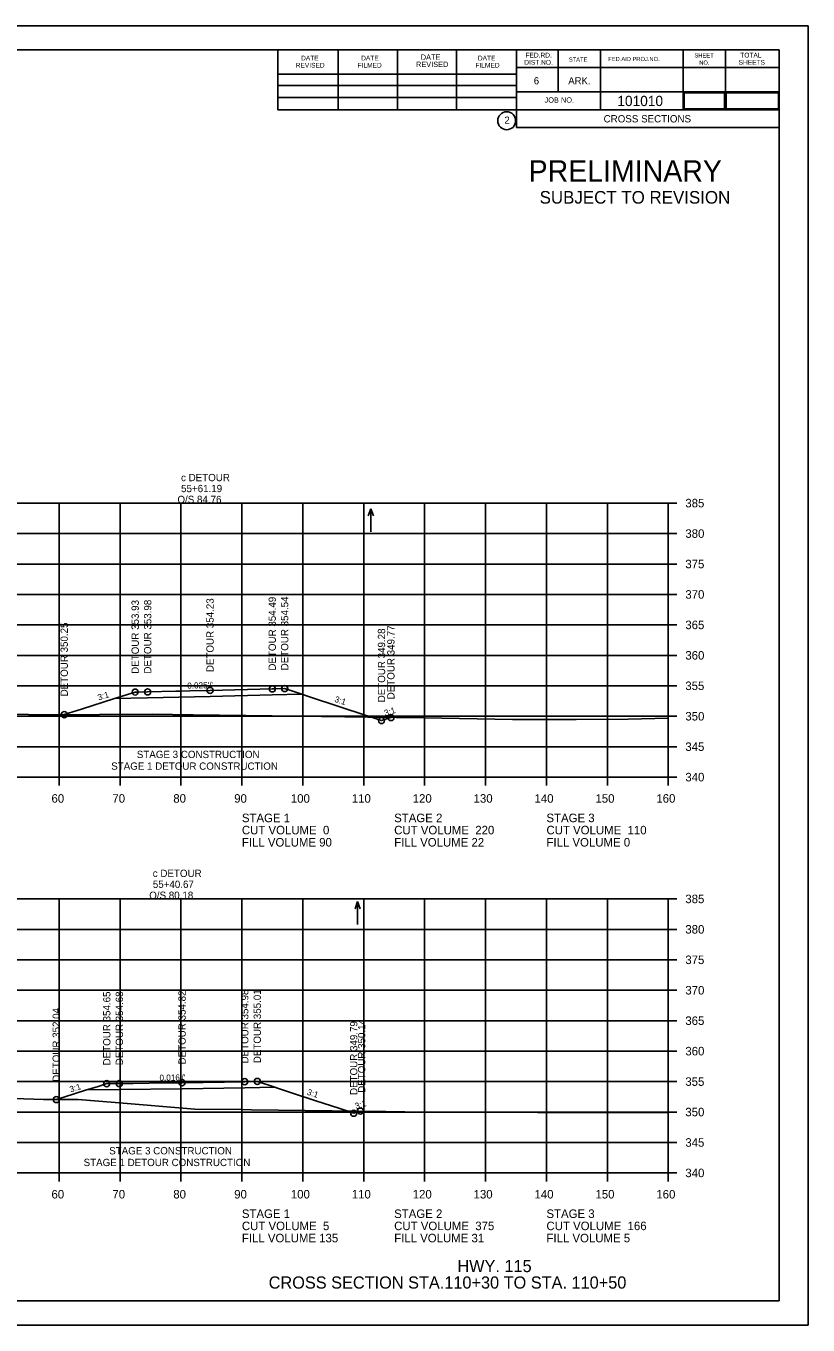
# Model space of a CAD drawing. Extents: x 1630712 to 1632516, y 782146 to 785403.
# Drawn here: x 1632387.5 to 1632515.9, y 784123.3 to 784336.6 of the extents above; entities that cross this region are included whole.
import ezdxf

# ---------------------------------------------------------------- set-up
doc = ezdxf.new("R2010")
doc.units = 0
for name, color, linetype in [('Notes', 7, 'Continuous'), ('Page Number', 7, 'Continuous'), ('R_Axis', 7, 'Continuous'), ('R_Axis Annot', 7, 'Continuous'), ('R_Border', 7, 'Continuous'), ('R_Border Notes', 7, 'Continuous'), ('R_Border Prem', 7, 'Continuous'), ('R_Detour Subgrade', 7, 'Continuous'), ('R_Detour Surface', 7, 'Continuous'), ('R_Draft', 7, 'Continuous'), ('R_Exist Surface', 7, 'Continuous'), ('R_Grid', 7, 'Continuous'), ('R_No Plot', 7, 'Continuous'), ('R_Water Annot', 7, 'Continuous'), ('R_Xsect Elev Detour', 7, 'Continuous'), ('R_Xsect Slope', 7, 'Continuous'), ('Total_Pages', 7, 'Continuous')]:
    doc.layers.add(name, color=color, linetype=linetype)

msp = doc.modelspace()

# ---------------------------------------------------------------- linework, layer by layer
at = {"layer": 'Page Number'}
msp.add_lwpolyline([(1632495.54, 784323.02), (1632502.21, 784323.02), (1632502.21, 784325.66), (1632495.54, 784325.66)], close=True, dxfattribs=at)
at = {"layer": 'R_Axis'}
for p, q in [((1632492.96, 784213.29), (1632492.96, 784258.29)), ((1632494.36, 784258.29), (1632492.96, 784258.29)), ((1632494.36, 784253.29), (1632492.96, 784253.29)), ((1632494.36, 784248.29), (1632492.96, 784248.29)), ((1632494.36, 784243.29), (1632492.96, 784243.29)), ((1632494.36, 784238.29), (1632492.96, 784238.29)), ((1632494.36, 784233.29), (1632492.96, 784233.29)), ((1632494.36, 784228.29), (1632492.96, 784228.29)), ((1632494.36, 784223.29), (1632492.96, 784223.29)), ((1632494.36, 784218.29), (1632492.96, 784218.29)), ((1632212.96, 784213.29), (1632492.96, 784213.29)), ((1632392.96, 784211.89), (1632392.96, 784213.29)), ((1632402.96, 784211.89), (1632402.96, 784213.29)), ((1632412.96, 784211.89), (1632412.96, 784213.29)), ((1632422.96, 784211.89), (1632422.96, 784213.29)), ((1632432.96, 784211.89), (1632432.96, 784213.29)), ((1632442.96, 784211.89), (1632442.96, 784213.29)), ((1632452.96, 784211.89), (1632452.96, 784213.29)), ((1632462.96, 784211.89), (1632462.96, 784213.29)), ((1632472.96, 784211.89), (1632472.96, 784213.29)), ((1632482.96, 784211.89), (1632482.96, 784213.29)), ((1632492.96, 784211.89), (1632492.96, 784213.29)), ((1632494.36, 784213.29), (1632492.96, 784213.29)), ((1632492.96, 784148.29), (1632492.96, 784193.29)), ((1632494.36, 784193.29), (1632492.96, 784193.29)), ((1632494.36, 784188.29), (1632492.96, 784188.29)), ((1632494.36, 784183.29), (1632492.96, 784183.29)), ((1632494.36, 784178.29), (1632492.96, 784178.29)), ((1632494.36, 784173.29), (1632492.96, 784173.29)), ((1632494.36, 784168.29), (1632492.96, 784168.29)), ((1632494.36, 784163.29), (1632492.96, 784163.29)), ((1632494.36, 784158.29), (1632492.96, 784158.29)), ((1632494.36, 784153.29), (1632492.96, 784153.29)), ((1632212.96, 784148.29), (1632492.96, 784148.29)), ((1632392.96, 784146.89), (1632392.96, 784148.29)), ((1632402.96, 784146.89), (1632402.96, 784148.29)), ((1632412.96, 784146.89), (1632412.96, 784148.29)), ((1632422.96, 784146.89), (1632422.96, 784148.29)), ((1632432.96, 784146.89), (1632432.96, 784148.29)), ((1632442.96, 784146.89), (1632442.96, 784148.29)), ((1632452.96, 784146.89), (1632452.96, 784148.29)), ((1632462.96, 784146.89), (1632462.96, 784148.29)), ((1632472.96, 784146.89), (1632472.96, 784148.29)), ((1632482.96, 784146.89), (1632482.96, 784148.29)), ((1632492.96, 784146.89), (1632492.96, 784148.29)), ((1632494.36, 784148.29), (1632492.96, 784148.29))]:
    msp.add_line(p, q, dxfattribs=at)
at = {"layer": 'R_Border'}
for p, q in [((1632194.96, 784332.75), (1632511.14, 784332.75)), ((1632428.88, 784322.87), (1632428.88, 784332.75)), ((1632438.74, 784322.87), (1632438.74, 784332.55)), ((1632448.5, 784322.87), (1632448.5, 784332.55)), ((1632458.18, 784322.87), (1632458.18, 784332.55)), ((1632468.04, 784332.75), (1632468.04, 784319.95)), ((1632474.88, 784332.75), (1632474.88, 784325.81)), ((1632481.82, 784332.75), (1632481.82, 784322.87)), ((1632495.4, 784332.75), (1632495.4, 784322.87)), ((1632502.34, 784332.75), (1632502.34, 784322.87)), ((1632511.14, 784127.29), (1632511.14, 784332.75)), ((1632511.14, 784329.81), (1632468.04, 784329.81)), ((1632511.14, 784329.83), (1632511.14, 784329.83)), ((1632428.88, 784328.73), (1632468.04, 784328.73)), ((1632428.88, 784326.87), (1632468.04, 784326.87)), ((1632511.14, 784325.81), (1632468.04, 784325.81)), ((1632471, 784325.81), (1632511.14, 784325.81)), ((1632428.88, 784322.87), (1632428.88, 784324.93)), ((1632428.88, 784324.93), (1632468.04, 784324.93)), ((1632511.14, 784322.87), (1632428.88, 784322.87)), ((1632468.04, 784319.95), (1632511.14, 784319.95)), ((1632511.14, 784127.29), (1632194.96, 784127.29))]:
    msp.add_line(p, q, dxfattribs=at)
msp.add_circle((1632466.43, 784321.09), 1.47, dxfattribs=at)
at = {"layer": 'R_Detour Subgrade'}
for points in [[(1632402.07, 784226.18), (1632407.49, 784226.29), (1632417.73, 784226.53), (1632427.94, 784226.78), (1632432.78, 784226.91)], [(1632397.47, 784161.91), (1632402.84, 784161.97), (1632413.14, 784162.11), (1632423.43, 784162.27), (1632428.36, 784162.36)]]:
    msp.add_lwpolyline(points, dxfattribs=at)
at = {"layer": 'R_Detour Surface'}
for points in [[(1632393.79, 784223.55), (1632396.64, 784224.45), (1632402.07, 784226.18), (1632404.92, 784227.09), (1632405.44, 784227.25), (1632405.72, 784227.26), (1632407.49, 784227.29), (1632412.09, 784227.4), (1632412.5, 784227.41), (1632412.92, 784227.41), (1632414.44, 784227.45), (1632417.72, 784227.53), (1632417.73, 784227.53), (1632417.73, 784227.53), (1632427.94, 784227.78), (1632428.45, 784227.8), (1632429.98, 784227.83), (1632430.83, 784227.55), (1632432.78, 784226.91), (1632433, 784226.84), (1632433.39, 784226.7), (1632439.51, 784224.68), (1632445.88, 784222.57), (1632446.37, 784222.73), (1632447.42, 784223.07)], [(1632392.48, 784160.33), (1632393.73, 784160.73), (1632397.47, 784161.91), (1632399.18, 784162.44), (1632400.78, 784162.95), (1632402.1, 784162.96), (1632402.84, 784162.97), (1632405.12, 784162.99), (1632410.32, 784163.07), (1632413.13, 784163.11), (1632413.14, 784163.11), (1632413.14, 784163.11), (1632413.14, 784163.11), (1632420.08, 784163.21), (1632423.43, 784163.27), (1632424.5, 784163.29), (1632425.48, 784163.31), (1632427.36, 784162.69), (1632428.36, 784162.36), (1632428.81, 784162.21), (1632428.98, 784162.16), (1632431.13, 784161.45), (1632435.12, 784160.13), (1632438.86, 784158.9), (1632441.32, 784158.09), (1632442, 784158.3), (1632442.42, 784158.44)]]:
    msp.add_lwpolyline(points, dxfattribs=at)
at = {"layer": 'R_Exist Surface'}
for points in [[(1632380.08, 784223.79), (1632387.91, 784223.59), (1632395.61, 784223.53), (1632399.58, 784223.56), (1632408.24, 784223.61), (1632414.96, 784223.51), (1632432.25, 784223.3), (1632443.61, 784223.12), (1632452.89, 784223), (1632467.38, 784222.75), (1632477.86, 784222.73), (1632486.4, 784222.82), (1632492.96, 784222.95)], [(1632380.71, 784160.67), (1632390.39, 784160.33), (1632396.09, 784160.34), (1632402.15, 784159.88), (1632415.22, 784158.78), (1632422.86, 784158.69), (1632424.55, 784158.66), (1632446.6, 784158.38), (1632452.91, 784158.27), (1632462.18, 784158.26), (1632471.5, 784158.22), (1632487.17, 784158.21), (1632489.76, 784158.2), (1632492.96, 784158.2)]]:
    msp.add_lwpolyline(points, dxfattribs=at)
at = {"layer": 'R_Grid'}
for p, q in [((1632212.96, 784258.29), (1632492.96, 784258.29)), ((1632392.96, 784213.29), (1632392.96, 784258.29)), ((1632402.96, 784213.29), (1632402.96, 784258.29)), ((1632412.96, 784213.29), (1632412.96, 784258.29)), ((1632422.96, 784213.29), (1632422.96, 784258.29)), ((1632432.96, 784213.29), (1632432.96, 784258.29)), ((1632442.96, 784213.29), (1632442.96, 784258.29)), ((1632452.96, 784213.29), (1632452.96, 784258.29)), ((1632462.96, 784213.29), (1632462.96, 784258.29)), ((1632472.96, 784213.29), (1632472.96, 784258.29)), ((1632482.96, 784213.29), (1632482.96, 784258.29)), ((1632492.96, 784213.29), (1632492.96, 784258.29)), ((1632212.96, 784253.29), (1632492.96, 784253.29)), ((1632212.96, 784248.29), (1632492.96, 784248.29)), ((1632212.96, 784243.29), (1632492.96, 784243.29)), ((1632212.96, 784238.29), (1632492.96, 784238.29)), ((1632212.96, 784233.29), (1632492.96, 784233.29)), ((1632212.96, 784228.29), (1632492.96, 784228.29)), ((1632212.96, 784223.29), (1632492.96, 784223.29)), ((1632212.96, 784218.29), (1632492.96, 784218.29)), ((1632212.96, 784213.29), (1632492.96, 784213.29)), ((1632212.96, 784193.29), (1632492.96, 784193.29)), ((1632392.96, 784148.29), (1632392.96, 784193.29)), ((1632402.96, 784148.29), (1632402.96, 784193.29)), ((1632412.96, 784148.29), (1632412.96, 784193.29)), ((1632422.96, 784148.29), (1632422.96, 784193.29)), ((1632432.96, 784148.29), (1632432.96, 784193.29)), ((1632442.96, 784148.29), (1632442.96, 784193.29)), ((1632452.96, 784148.29), (1632452.96, 784193.29)), ((1632462.96, 784148.29), (1632462.96, 784193.29)), ((1632472.96, 784148.29), (1632472.96, 784193.29)), ((1632482.96, 784148.29), (1632482.96, 784193.29)), ((1632492.96, 784148.29), (1632492.96, 784193.29)), ((1632212.96, 784188.29), (1632492.96, 784188.29)), ((1632212.96, 784183.29), (1632492.96, 784183.29)), ((1632212.96, 784178.29), (1632492.96, 784178.29)), ((1632212.96, 784173.29), (1632492.96, 784173.29)), ((1632212.96, 784168.29), (1632492.96, 784168.29)), ((1632212.96, 784163.29), (1632492.96, 784163.29)), ((1632212.96, 784158.29), (1632492.96, 784158.29)), ((1632212.96, 784153.29), (1632492.96, 784153.29)), ((1632212.96, 784148.29), (1632492.96, 784148.29))]:
    msp.add_line(p, q, dxfattribs=at)
at = {"layer": 'R_No Plot'}
for p, q in [((1632182.56, 784336.65), (1632515.9, 784336.65)), ((1632182.56, 784123.31), (1632515.9, 784123.31))]:
    msp.add_line(p, q, dxfattribs=at)
msp.add_lwpolyline([(1632182.56, 784336.65), (1632515.9, 784336.65), (1632515.9, 784123.31), (1632182.56, 784123.31)], close=True, dxfattribs=at)
for centre in [(1632405.44, 784227.25), (1632407.49, 784227.29), (1632417.73, 784227.53), (1632427.94, 784227.78), (1632429.98, 784227.83), (1632393.79, 784223.55), (1632445.88, 784222.57), (1632447.42, 784223.07), (1632400.78, 784162.95), (1632402.84, 784162.97), (1632413.14, 784163.11), (1632423.43, 784163.27), (1632425.48, 784163.31), (1632392.48, 784160.33), (1632442.42, 784158.44), (1632441.32, 784158.09)]:
    msp.add_circle(centre, 0.5, dxfattribs=at)
at = {"layer": 'R_Water Annot'}
for p, q in [((1632444.13, 784257.35), (1632443.71, 784256.19)), ((1632444.13, 784253.58), (1632444.13, 784257.35)), ((1632444.13, 784257.35), (1632444.55, 784256.19)), ((1632441.96, 784192.84), (1632441.54, 784191.68)), ((1632441.96, 784189.07), (1632441.96, 784192.84)), ((1632441.96, 784192.84), (1632442.38, 784191.68))]:
    msp.add_line(p, q, dxfattribs=at)
at = {"layer": 'Total_Pages'}
msp.add_lwpolyline([(1632502.44, 784323.02), (1632511.05, 784323.02), (1632511.05, 784325.66), (1632502.44, 784325.66)], close=True, dxfattribs=at)

# ---------------------------------------------------------------- texts
at = {"layer": 'Notes'}
for s, p in [('c DETOUR', (1632412.97, 784261.89)), ('55+61.19', (1632412.98, 784260.09)), ('O/S 84.76', (1632412.38, 784258.29)), ('STAGE 3 CONSTRUCTION', (1632405.71, 784216.42)), ('STAGE 1 DETOUR CONSTRUCTION', (1632401.51, 784214.5)), ('c DETOUR', (1632408.33, 784196.89)), ('55+40.67', (1632408.34, 784195.09)), ('O/S 80.18', (1632407.75, 784193.29)), ('STAGE 3 CONSTRUCTION', (1632401.18, 784151.33)), ('STAGE 1 DETOUR CONSTRUCTION', (1632396.98, 784149.41))]:
    msp.add_text(s, height=1.2, dxfattribs=at).set_placement(p)
at = {"layer": 'R_Axis Annot'}
for s, p in [('385', (1632495.76, 784257.59)), ('380', (1632495.76, 784252.59)), ('375', (1632495.76, 784247.59)), ('370', (1632495.76, 784242.59)), ('365', (1632495.76, 784237.59)), ('360', (1632495.76, 784232.59)), ('355', (1632495.76, 784227.59)), ('350', (1632495.76, 784222.59)), ('345', (1632495.76, 784217.59)), ('340', (1632495.76, 784212.59)), ('60', (1632391.7, 784209.09)), ('70', (1632401.7, 784209.09)), ('80', (1632411.7, 784209.09)), ('90', (1632421.7, 784209.09)), ('100', (1632431, 784209.09)), ('110', (1632441, 784209.09)), ('120', (1632451, 784209.09)), ('130', (1632461, 784209.09)), ('140', (1632471, 784209.09)), ('150', (1632481, 784209.09)), ('160', (1632491, 784209.09)), ('STAGE 1', (1632422.96, 784205.89)), ('STAGE 2', (1632447.96, 784205.89)), ('STAGE 3', (1632472.96, 784205.89)), ('CUT VOLUME  0', (1632422.96, 784203.89)), ('CUT VOLUME  220', (1632447.96, 784203.89)), ('CUT VOLUME  110', (1632472.96, 784203.89)), ('FILL VOLUME 90', (1632422.96, 784201.89)), ('FILL VOLUME 22', (1632447.96, 784201.89)), ('FILL VOLUME 0', (1632472.96, 784201.89)), ('385', (1632495.76, 784192.59)), ('380', (1632495.76, 784187.59)), ('375', (1632495.76, 784182.59)), ('370', (1632495.76, 784177.59)), ('365', (1632495.76, 784172.59)), ('360', (1632495.76, 784167.59)), ('355', (1632495.76, 784162.59)), ('350', (1632495.76, 784157.59)), ('345', (1632495.76, 784152.59)), ('340', (1632495.76, 784147.59)), ('60', (1632391.7, 784144.09)), ('70', (1632401.7, 784144.09)), ('80', (1632411.7, 784144.09)), ('90', (1632421.7, 784144.09)), ('100', (1632431, 784144.09)), ('110', (1632441, 784144.09)), ('120', (1632451, 784144.09)), ('130', (1632461, 784144.09)), ('140', (1632471, 784144.09)), ('150', (1632481, 784144.09)), ('160', (1632491, 784144.09)), ('STAGE 1', (1632422.96, 784140.89)), ('STAGE 2', (1632447.96, 784140.89)), ('STAGE 3', (1632472.96, 784140.89)), ('CUT VOLUME  5', (1632422.96, 784138.89)), ('CUT VOLUME  375', (1632447.96, 784138.89)), ('CUT VOLUME  166', (1632472.96, 784138.89)), ('FILL VOLUME 135', (1632422.96, 784136.89)), ('FILL VOLUME 31', (1632447.96, 784136.89)), ('FILL VOLUME 5', (1632472.96, 784136.89))]:
    msp.add_text(s, height=1.4, dxfattribs=at).set_placement(p)
at = {"layer": 'R_Border'}
for s, height, p in [('DATE', 0.782, (1632432.68, 784330.99)), ('DATE', 0.782, (1632442.54, 784330.99)), ('DATE', 0.879, (1632452.32, 784331.09)), ('DATE', 0.782, (1632461.7, 784330.99)), ('FED.RD.', 0.782, (1632469.52, 784331.47)), ('STATE', 0.684, (1632476.64, 784330.79)), ('FED.AID PROJ.NO.', 0.684, (1632483.1, 784330.89)), ('SHEET', 0.684, (1632497.26, 784331.47)), ('TOTAL', 0.782, (1632504.78, 784331.47)), ('REVISED', 0.782, (1632431.8, 784329.81)), ('FILMED', 0.782, (1632441.96, 784329.81)), ('REVISED', 0.879, (1632451.54, 784329.91)), ('FILMED', 0.782, (1632461.3, 784329.81)), ('DIST.NO.', 0.782, (1632469.32, 784330.29)), ('NO.', 0.684, (1632498.04, 784330.29)), ('SHEETS', 0.782, (1632504.5, 784330.29)), ('6', 1.17, (1632470.88, 784327.07)), ('ARK.', 1.172, (1632476.54, 784327.07)), ('JOB NO.', 0.879, (1632472.64, 784324.05)), ('2', 1.17, (1632466.05, 784320.6))]:
    msp.add_text(s, height=height, rotation=360, dxfattribs=at).set_placement(p)
at = {"layer": 'R_Border Notes'}
for s, height, p in [('101010', 1.68, (1632484.6, 784323.5)), ('CROSS SECTIONS', 1.2, (1632482.34, 784320.81))]:
    msp.add_text(s, height=height, dxfattribs=at).set_placement(p)
at = {"layer": 'R_Border Prem'}
for s, height, p in [('PRELIMINARY', 3.5, (1632470.03, 784311.1)), ('SUBJECT TO REVISION', 2.0751, (1632471.84, 784307.47))]:
    msp.add_text(s, height=height, rotation=360, dxfattribs=at).set_placement(p)
at = {"layer": 'R_Draft'}
for s, p in [('HWY. 115', (1632458.34, 784132)), ('CROSS SECTION STA.110+30 TO STA. 110+50', (1632427.36, 784129.29))]:
    msp.add_text(s, height=2, dxfattribs=at).set_placement(p)
at = {"layer": 'R_Xsect Elev Detour'}
for s, p in [('DETOUR 353.93', (1632406.04, 784230.25)), ('DETOUR 353.98', (1632408.09, 784230.29)), ('DETOUR 354.23', (1632418.33, 784230.53)), ('DETOUR 354.49', (1632428.54, 784230.78)), ('DETOUR 354.54', (1632430.58, 784230.83)), ('DETOUR 350.25', (1632394.39, 784226.55)), ('DETOUR 349.28', (1632446.48, 784225.57)), ('DETOUR 349.77', (1632448.02, 784226.07)), ('DETOUR 354.65', (1632401.38, 784165.95)), ('DETOUR 354.68', (1632403.44, 784165.97)), ('DETOUR 354.82', (1632413.74, 784166.11)), ('DETOUR 354.98', (1632424.03, 784166.27)), ('DETOUR 355.01', (1632426.08, 784166.31)), ('DETOUR 352.04', (1632393.08, 784163.25)), ('DETOUR 349.79', (1632441.92, 784161.09)), ('DETOUR 350.14', (1632443.22, 784161.44))]:
    msp.add_text(s, height=1.2, rotation=90, dxfattribs=at).set_placement(p)
at = {"layer": 'R_Xsect Slope'}
for s, rotation, p in [('3:1', 17.648, (1632399.47, 784225.87)), ("0.025'/'", 1.4337, (1632414, 784227.81)), ('3:1', 341.6958, (1632438.09, 784225.68)), ('3:1', 17.7783, (1632446.5, 784223.3)), ('3:1', 17.4774, (1632394.86, 784161.5)), ("0.016'/'", 0.9186, (1632409.44, 784163.42)), ('3:1', 341.7488, (1632433.56, 784161.17)), ('3:1', 17.6658, (1632441.71, 784158.74))]:
    msp.add_text(s, height=1, rotation=rotation, dxfattribs=at).set_placement(p)

doc.saveas('drawing.dxf')
